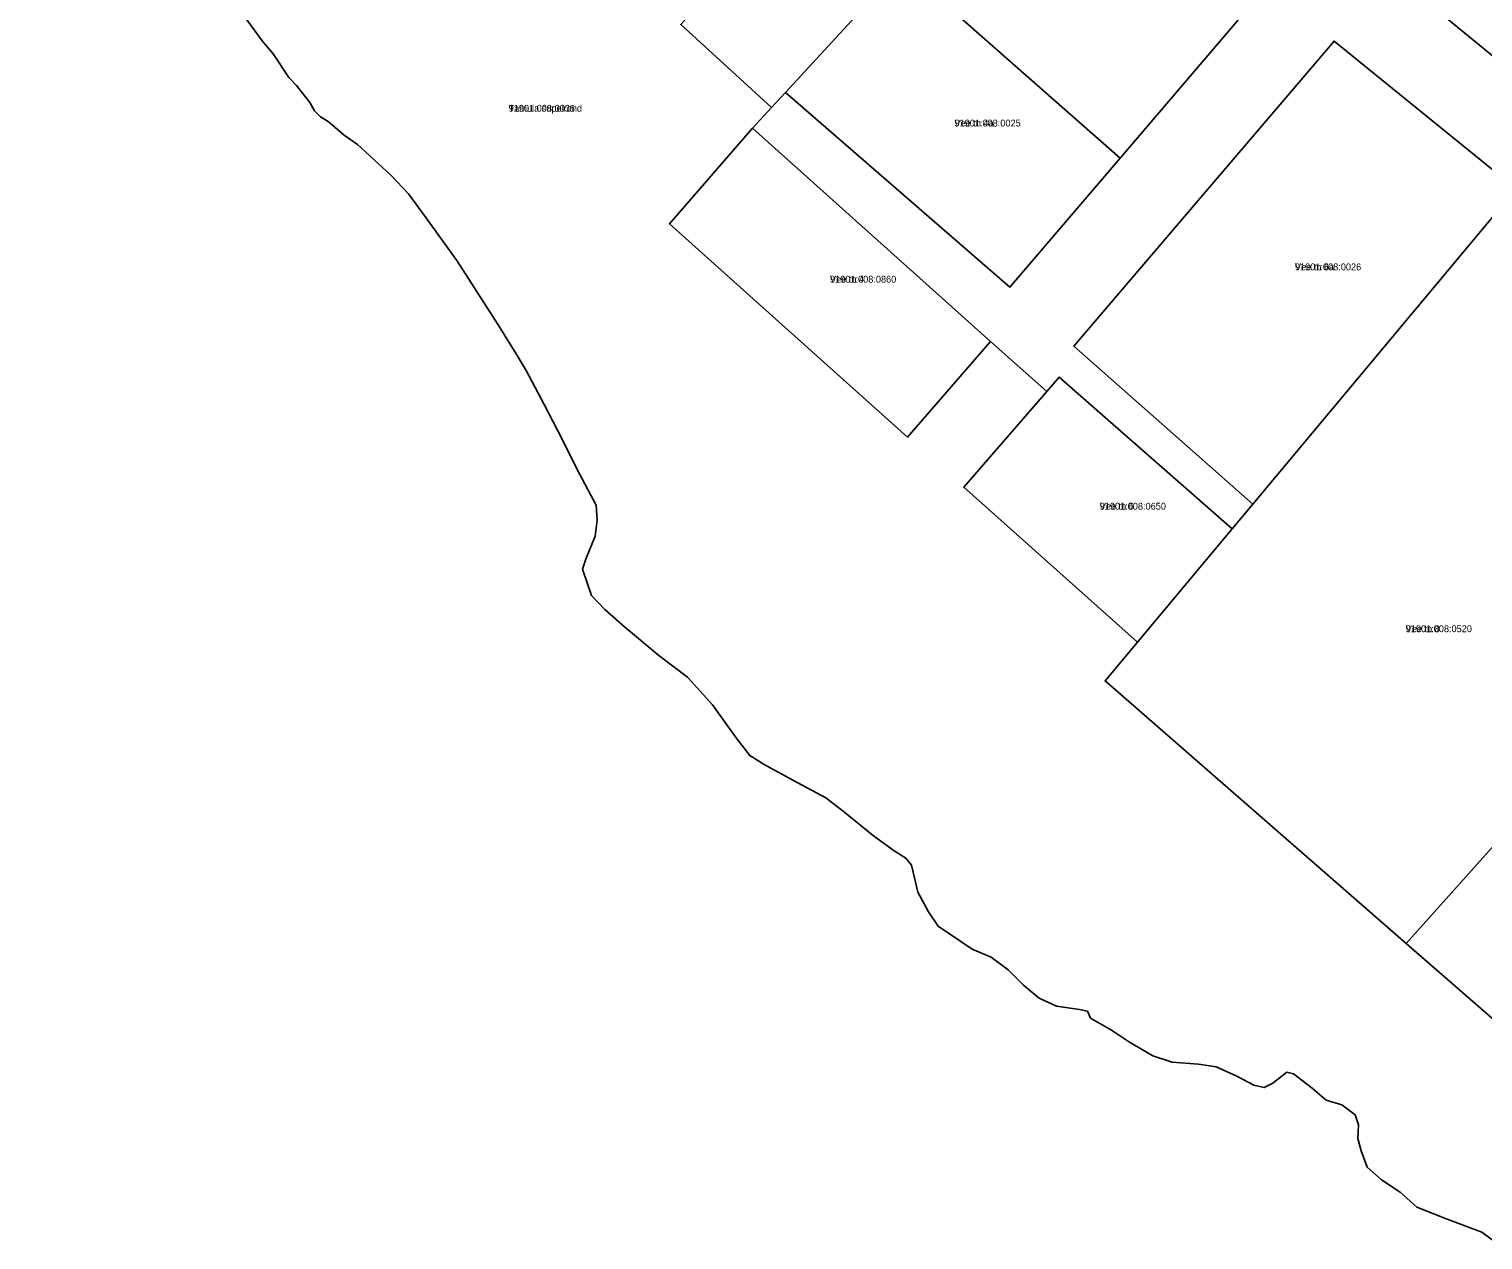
# Model space of a CAD drawing. Extents: x 675810 to 681273, y 6411190 to 6417565.
# Drawn here: x 677508.4 to 677826.5, y 6415023.4 to 6415288.2 of the extents above; entities that cross this region are included whole.
import ezdxf

# ---------------------------------------------------------------- set-up
doc = ezdxf.new("R2010")
doc.units = 0
for name, color, linetype in [('L_AADRESS', 7, 'Continuous'), ('PIIR', 7, 'Continuous'), ('TUNNUS', 7, 'Continuous')]:
    doc.layers.add(name, color=color, linetype=linetype)

msp = doc.modelspace()

# ---------------------------------------------------------------- linework, layer by layer
at = {"layer": 'PIIR'}
for points in [[(677485.36, 6415406.68), (677550.88, 6415368.11), (677554.69, 6415367.45), (677566.49, 6415356.58), (677601.8, 6415332.63), (677603.77, 6415328.68), (677622.25, 6415312.81), (677625.2, 6415315.85), (677652.45, 6415290.88), (677650.98, 6415289.25), (677670.83, 6415271.06), (677666.68, 6415266.54), (677648.5, 6415245.63), (677700.59, 6415199.01), (677718.76, 6415219.92), (677731.04, 6415208.96), (677712.89, 6415188.04), (677750.89, 6415154.12), (677743.82, 6415145.67), (677809.68, 6415088.2), (677848.98, 6415054.08)], [(677806.4, 6415300.64), (677832.58, 6415279.14)], [(677833.78, 6415253.28), (677793.94, 6415285.62), (677736.95, 6415218.9), (677776.13, 6415184.33), (677771.65, 6415178.95), (677733.8, 6415212.13), (677731.04, 6415208.96), (677718.76, 6415219.92), (677666.68, 6415266.54), (677670.83, 6415271.06), (677673.87, 6415274.36), (677722.98, 6415231.8), (677747.14, 6415260.04), (677779.53, 6415298.01)], [(677555.03, 6415291.57), (677559.39, 6415285.68), (677561.75, 6415282.87), (677565.19, 6415277.65), (677566.88, 6415275.88), (677569.8, 6415272.21), (677570.78, 6415270.38), (677572.15, 6415269.09), (677573.82, 6415268.05), (677577.28, 6415265.02), (677580.24, 6415262.99), (677587.54, 6415256.3), (677591.35, 6415252.24), (677595.21, 6415247), (677601.95, 6415237.66), (677610.98, 6415223.53), (677614.98, 6415217.19), (677617.1, 6415213.58), (677621.07, 6415206.11), (677624.02, 6415200.49), (677628.9, 6415190.84), (677632.42, 6415184.08), (677632.64, 6415180.83), (677632.25, 6415177.3), (677630.28, 6415172.53), (677629.49, 6415170.07), (677631.44, 6415164.34), (677634.33, 6415161.3), (677638.64, 6415157.49), (677646.19, 6415151.21), (677652.47, 6415146.49), (677657.9, 6415140.42), (677663.12, 6415133.22), (677666.08, 6415129.34), (677669.19, 6415127.37), (677675.47, 6415123.98), (677682.73, 6415120.1), (677686.47, 6415117.13), (677693.18, 6415111.77), (677697.69, 6415108.46), (677700.23, 6415106.9), (677701.43, 6415105.35), (677702.07, 6415102.88), (677702.84, 6415099.42), (677705.17, 6415095.12), (677707.29, 6415092.02), (677714.7, 6415086.94), (677718.86, 6415085.24), (677722.6, 6415082.42), (677725.99, 6415079.11), (677729.37, 6415076.28), (677733.19, 6415074.52), (677738.19, 6415073.81), (677739.96, 6415073.39), (677740.66, 6415071.91), (677745.25, 6415069.23), (677749.2, 6415066.62), (677754.28, 6415063.65), (677758.51, 6415062.24), (677764.3, 6415061.82), (677768.11, 6415061.25), (677772.69, 6415059.21), (677776.36, 6415057.23), (677778.62, 6415056.74), (677780.55, 6415057.65), (677783.63, 6415060.05), (677785.04, 6415059.7), (677789.13, 6415056.53), (677792.17, 6415053.92), (677795.62, 6415052.93), (677798.52, 6415050.74), (677799.29, 6415048.55), (677799.15, 6415045.59), (677799.86, 6415042.84), (677801.2, 6415039.31), (677804.3, 6415036.49), (677808.4, 6415033.81), (677812.06, 6415030.56), (677818.65, 6415027.92), (677826.24, 6415025.06), (677828.5, 6415023.37)], [(677828.5, 6415023.37), (677826.24, 6415025.06), (677818.65, 6415027.92), (677812.06, 6415030.56), (677808.4, 6415033.81), (677804.3, 6415036.49), (677801.2, 6415039.31), (677799.86, 6415042.84), (677799.15, 6415045.59), (677799.29, 6415048.55), (677798.52, 6415050.74), (677795.62, 6415052.93), (677792.17, 6415053.92), (677789.13, 6415056.53), (677785.04, 6415059.7), (677783.63, 6415060.05), (677780.55, 6415057.65), (677778.62, 6415056.74), (677776.36, 6415057.23), (677772.69, 6415059.21), (677768.11, 6415061.25), (677764.3, 6415061.82), (677758.51, 6415062.24), (677754.28, 6415063.65), (677749.2, 6415066.62), (677745.25, 6415069.23), (677740.66, 6415071.91), (677739.96, 6415073.39), (677738.19, 6415073.81), (677733.19, 6415074.52), (677729.37, 6415076.28), (677725.99, 6415079.11), (677722.6, 6415082.42), (677718.86, 6415085.24), (677714.7, 6415086.94), (677707.29, 6415092.02), (677705.17, 6415095.12), (677702.84, 6415099.42), (677702.07, 6415102.88), (677701.43, 6415105.35), (677700.23, 6415106.9), (677697.69, 6415108.46), (677693.18, 6415111.77), (677686.47, 6415117.13), (677682.73, 6415120.1), (677675.47, 6415123.98), (677669.19, 6415127.37), (677666.08, 6415129.34), (677663.12, 6415133.22), (677657.9, 6415140.42), (677652.47, 6415146.49), (677646.19, 6415151.21), (677638.64, 6415157.49), (677634.33, 6415161.3), (677631.44, 6415164.34), (677629.49, 6415170.07), (677630.28, 6415172.53), (677632.25, 6415177.3), (677632.64, 6415180.83), (677632.42, 6415184.08), (677628.9, 6415190.84), (677624.02, 6415200.49), (677621.07, 6415206.11), (677617.1, 6415213.58), (677614.98, 6415217.19), (677610.98, 6415223.53), (677601.95, 6415237.66), (677595.21, 6415247), (677591.35, 6415252.24), (677587.54, 6415256.3), (677580.24, 6415262.99), (677577.28, 6415265.02), (677573.82, 6415268.05), (677572.15, 6415269.09), (677570.78, 6415270.38), (677569.8, 6415272.21), (677566.88, 6415275.88), (677565.19, 6415277.65), (677561.75, 6415282.87), (677559.39, 6415285.68), (677555.03, 6415291.57)]]:
    msp.add_lwpolyline(points, dxfattribs=at)
for points in [[(677713.15, 6415356.53), (677779.53, 6415298.01), (677747.14, 6415260.04), (677699.36, 6415302.08), (677679.14, 6415319.9)], [(677826.76, 6415323.27), (677851.33, 6415301.12), (677832.58, 6415279.14), (677806.4, 6415300.64)], [(677679.14, 6415319.9), (677699.36, 6415302.08), (677673.87, 6415274.36), (677670.83, 6415271.06), (677650.98, 6415289.25), (677652.45, 6415290.88), (677673.45, 6415313.78)], [(677699.36, 6415302.08), (677747.14, 6415260.04), (677722.98, 6415231.8), (677673.87, 6415274.36)], [(677793.94, 6415285.62), (677833.78, 6415253.28), (677776.13, 6415184.33), (677736.95, 6415218.9)], [(677718.76, 6415219.92), (677700.59, 6415199.01), (677648.5, 6415245.63), (677666.68, 6415266.54)], [(677809.68, 6415088.2), (677743.82, 6415145.67), (677750.89, 6415154.12), (677771.65, 6415178.95), (677776.13, 6415184.33), (677833.78, 6415253.28), (677874.3, 6415220.63), (677864.87, 6415208.84), (677875.38, 6415200.45), (677872.93, 6415190.08), (677845.5, 6415160.96), (677853.28, 6415136.87)], [(677771.65, 6415178.95), (677750.89, 6415154.12), (677712.89, 6415188.04), (677731.04, 6415208.96), (677733.8, 6415212.13)], [(677886.45, 6415097), (677848.98, 6415054.08), (677809.68, 6415088.2), (677853.28, 6415136.87), (677873.07, 6415123.73), (677893.77, 6415106.07)]]:
    msp.add_lwpolyline(points, close=True, dxfattribs=at)

# ---------------------------------------------------------------- texts
at = {"layer": 'L_AADRESS'}
for s, p in [('Tamula supelrand', (677613.3, 6415270.17)), ('Vee tn 4a', (677710.86, 6415266.94)), ('Vee tn 6a', (677785.37, 6415235.48)), ('Vee tn 4', (677683.63, 6415232.78)), ('Vee tn 6', (677742.64, 6415183.12)), ('Vee tn 8', (677809.6, 6415156.32))]:
    msp.add_text(s, height=1.5, dxfattribs=at).set_placement(p)
at = {"layer": 'TUNNUS'}
for s, p in [('91901:008:0035', (677613.3, 6415270.17)), ('91901:008:0025', (677710.86, 6415266.94)), ('91901:008:0026', (677785.37, 6415235.48)), ('91901:008:0860', (677683.63, 6415232.78)), ('91901:008:0650', (677742.64, 6415183.12)), ('91901:008:0520', (677809.6, 6415156.32))]:
    msp.add_text(s, height=1.5, dxfattribs=at).set_placement(p)

doc.saveas('drawing.dxf')
